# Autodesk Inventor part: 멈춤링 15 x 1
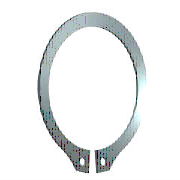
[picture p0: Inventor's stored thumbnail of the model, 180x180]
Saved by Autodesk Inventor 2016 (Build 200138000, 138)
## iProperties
IsCustomPart: 1
Created: 2012-02
Part Number: 멈춤링 15 x 1
Material: 강철, 연강
Description: 리테이닝 링(C형)
Document SubType Name: Modeling
Standard: KS B 1336
Designer: mduedu
Standards Organization: KS
Language: ko-KR
Size Designation: 15 x 1
Categories: <MemberInstance><Categories><Category DisplayName="샤프트 부품" InternalName="7f7aeb1f-a693-4053-b835-cee3144e0d98" Mnemonic="SHFT"><Category DisplayName="써클립" Inter
Density: 1 g/cm^3
Appearance: 파란색 - 벽 페인트 - 광택
Author: mduedu
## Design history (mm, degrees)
sketch "스케치1"
  geometry: L1 (-6, 0)-(6, 0) reference; L2 (0, 20.189)-(0, -80.536) reference; L3 (-48.09, 0)-(48.09, 0) reference; L4 (-0.425, -14.637)-(-0.425, -18.137); L5 (-0.425, -6.54)-(-0.425, -13.29); L6 (-2.795, 2.1)-(3.672, 2.1); L7 (0.425, -6.54)-(0.425, -13.29); L8 (0.425, -14.637)-(0.425, -18.137); C1 r 0.85 at (-1.7, -16.283); C2 r 0.85 at (1.7, -16.283); A1 r 7.15 centre (0, -7.5) between (0.425, -14.637) and (-0.425, -14.637); A2 r 9.075 centre (0, -6.975) between (4.291, -14.971) and (-4.291, -14.971); A3 r 10.646 centre (0, -7.5) between (-2.023, -17.952) and (-0.425, -18.137); A4 r 1.7 centre (-1.7, -16.283) between (-3.397, -16.376) and (-2.023, -17.952); A5 r 1.7 centre (-5.095, -16.469) between (-3.397, -16.376) and (-4.291, -14.971); A6 r 1.7 centre (5.095, -16.469) between (4.291, -14.971) and (3.397, -16.376); A7 r 1.7 centre (1.7, -16.283) between (2.023, -17.952) and (3.397, -16.376); A8 r 10.646 centre (0, -7.5) between (0.425, -18.137) and (2.023, -17.952)
  constraints: 16 point on circle, 12 end point, 10 centre point, 9 symmetric about line, 5 point on line, 4 tangent, 3 coincident, 2 horizontal, 1 perpendicular, 1 vertical, 5 other
  dimensions: "d0" = 14.3 diameter of A1 (= ND); "d1" = 3.5 distance of L4.end L4.start (= SRB2); "d6" = 0.425 distance between parallel lines of L2 L5 (= 0.25 x SD5); "d7" = 2.1 distance between parallel lines of L6 L3 (= SRB1); "d8" = 0.525 distance of A1.centre A2.centre (= 0.25 x SRB1); "d9" = 1.7 radius of A4 (= SD5); "d10" = 1.7 radius of A5 (= SD5); "d11" = 1.275 distance from line of L4 A4.centre (= 0.75 x SD5); "d12" = 1.7 diameter of C1 (= SD5); "d13" = 1.7 diameter of C2 (= SD5); "d14" = 7.5 distance from line of A1.centre L1 (= 0.5 x WD)
extrude "본체" new body sketch "스케치1" distance "d2" = 1 (= SD); taper "d3" = 0 deg
workaxis "Work Axis1"
workplane "Work Plane1"
body "Solid1"
other parameters: "WD" = 15 (= WDMIN) [user parameter; used in 1 equation term], "SD" = 1 [user parameter; used in 1 equation term], "SRB1" = 2.1 [user parameter; used in 2 equation terms], "ND" = 14.3 [user parameter; used in 1 equation term], "SRB2" = 3.5 [user parameter; used in 1 equation term], "SD5" = 1.7 [user parameter; used in 6 equation terms], "d15" = 0, "d16" = 0, "d17" = 0, "d41" = 0, "d42" = 0, "WDMIN" = 15 [user parameter; used in 1 equation term], "SD3" = 13.8 [user parameter], "WDMAX" = 16 [user parameter]
